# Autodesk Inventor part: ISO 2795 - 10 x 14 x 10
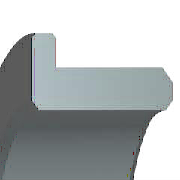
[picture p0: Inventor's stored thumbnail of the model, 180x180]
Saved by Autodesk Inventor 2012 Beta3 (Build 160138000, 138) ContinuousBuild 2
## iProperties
IsCustomPart: 0
Created: 2010-02
Part Number: ISO 2795 - 10 x 14 x 10
Material: Copper Alloy
Description: Plain bearing-Sintered bushes-Dimention and tolerances - Flanged Bearings
Document SubType Name: Modeling
Standard: ISO 2795
Designer: Thom Tremblay
Standard Revision: Fourth edition 1991-11-01
Standards Organization: ISO
Language: en-US
Size Designation: 10 x 14 x 10
Categories: <MemberInstance><Categories><Category DisplayName="Shaft Parts" InternalName="7f7aeb1f-a693-4053-b835-cee3144e0d98" Mnemonic="SHFT"><Category DisplayName="Beari
Density: 7.58 g/cm^3
Author: Thom Tremblay
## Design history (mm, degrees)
revolve "Body" stored, may be unused: angle "d3" = 90 deg
body "Solid1"
chamfer "Chamfer1" distance "d8" = 0.4001 (computed from WD, KID2); stored, may be unused: second distance "d9" = 0.4001 (computed from PHH4), angle "d32" = 45 deg
chamfer "Chamfer2" distance "d10" = 0.4001 (computed from KAD2, BD); stored, may be unused: second distance "d11" = 0.4001 (computed from PHH1), angle "d33" = 45 deg
chamfer "Chamfer3" distance "d22" = 0.4001 (computed from PHH5); stored, may be unused: second distance "d23" = 0.4001 (computed from PHH2), angle "d34" = 45 deg
chamfer "Chamfer4" distance "d24" = 0.4001 (computed from PHH5); stored, may be unused: second distance "d25" = 0.4001 (computed from PHH5), angle "d35" = 45 deg
chamfer "Chamfer5" distance "d26" = 0.4001 (computed from WD, KID1); stored, may be unused: second distance "d27" = 0.4001 (computed from PHH3), angle "d36" = 45 deg
sketch "Sketch"
  geometry: L1 (0, 0)-(10, 0); L2 (0, 0)-(0, 5); L3 (0, 5)-(10, 5); L4 (10, 5)-(10, 7); L5 (10, 7)-(2.6, 7); L6 (0, 9)-(0, 5); L7 (0, 9)-(2, 9); L8 (2, 9)-(2, 7.6); A1 r 0.6 centre (2.6, 7.6) between (2, 7.6) and (2.6, 7); 1 further point
  constraints: 16 end point, 3 parallel, 2 horizontal, 2 perpendicular, 2 point on circle, 2 point on line, 2 tangent, 1 centre point, 1 vertical
  dimensions: "d0" = 10 diameter of L3 L1 (= WD); "d1" = 14 diameter of L5 L1 (= BD); "d2" = 10 distance of L2.end L3.end (= KB); "d14" = 18 diameter of L7 L1 (= KAD1); "d20" = 2 distance of L6.start L7.end (= SD); "d38" = 0.6 radius of A1 (= R)
other parameters: "WD" = 10 [user parameter; used in 4 equation terms], "BD" = 14 [user parameter; used in 3 equation terms], "KB" = 10 [user parameter; used in 1 equation term], "PHH1" = 0.4 [user parameter; used in 5 equation terms], "KID1" = 10.8 [user parameter; used in 2 equation terms], "KAD1" = 18 [user parameter; used in 1 equation term], "PHH2" = 0.4 (= PHH1) [user parameter; used in 1 equation term], "PHH3" = 0.4 (= PHH1) [user parameter; used in 1 equation term], "PHH4" = 0.4 (= PHH1) [user parameter; used in 1 equation term], "KID2" = 10.8 (= KID1) [user parameter; used in 1 equation term], "KAD2" = 13.2 [user parameter; used in 1 equation term], "SD" = 2 [user parameter; used in 1 equation term], "STI" = 0.2 [user parameter], "SBR" = 2 [user parameter], "PHH5" = 0.4 (= PHH1) [user parameter; used in 3 equation terms], "d28" = 0, "d30" = 0, "d31" = 0, "R" = 0.6 [user parameter; used in 1 equation term], "WR" = 5 (= 0.5 x WD) [user parameter], "BC" = 1000000 [user parameter], "BR" = 7 (= 0.5 x BD) [user parameter], "BBA" = 0 [user parameter], "BC0" = 1000000 [user parameter]
